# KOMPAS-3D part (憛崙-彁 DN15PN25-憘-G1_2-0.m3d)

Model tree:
1. Объединить компоненты:1  (labels: СЕНС-ПР DN15PN25-G1/2-0)
2. Эскиз:1
3. Операция выдавливания:1
     Расстояние 1 = 14
4. Фаска:1
     Угол = 45; Длина 1 = 2; Длина 2 = 2

Referenced files in D:\Савин\!СЕНСОР\3D для заказчика\!Новый перечень\СЕНС-ПР\6. СЕНС-ПР-G\DN15\: СЕНС-ПР DN15PN25-G1_2-0.a3d
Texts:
  СЕНС-ПР DN15PN25-СВ-G1/2-0
  СЕНС-ПР DN15PN25-G1/2-0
